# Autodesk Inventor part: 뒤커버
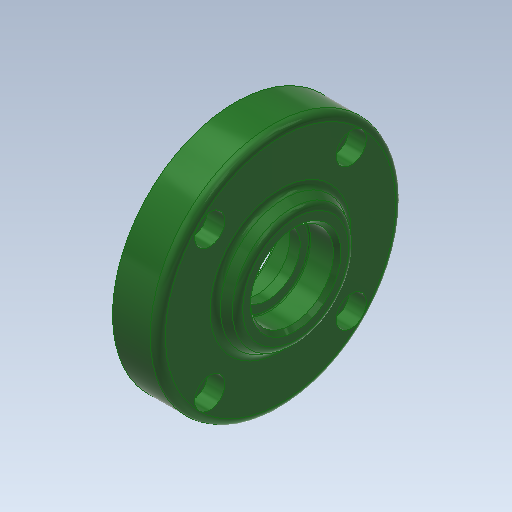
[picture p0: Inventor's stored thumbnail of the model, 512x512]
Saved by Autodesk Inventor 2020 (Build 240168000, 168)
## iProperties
Created: 2015-12
Part Number: 뒤커버
Document SubType Name: Modeling
Designer: mdu
Density: 2.71 g/cm^3
Mass: 96.0617 g
Surface Area: 117.44 cm^2
Volume: 35.4471 cm^3
Material: 알루미늄-6061
Appearance: 매끄러움 - 짙은 산림 녹색
Company: 한국ATC센터
Author: mdu
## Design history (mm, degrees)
sketch "스케치1"
  geometry: L1 (-10.5, 0)-(10.5, 0); L2 (10.5, 0)-(10.5, 22.5); L3 (10.5, 22.5)-(5.5, 22.5); L4 (5.5, 22.5)-(5.5, 32.5); L5 (5.5, 32.5)-(-6.5, 32.5); L6 (-6.5, 32.5)-(-6.5, 17.5); L7 (-6.5, 17.5)-(-10.5, 15.191); L8 (-10.5, 15.191)-(-10.5, 0); 2 further points
  constraints: 16 end point, 3 parallel, 3 perpendicular, 1 coincident, 1 horizontal, 1 midpoint
  dimensions: "d0" = 21 distance of L1.start L1.end; "d1" = 65 diameter of L5 L1; "d2" = 45 diameter of L3 L1; "d3" = 35 diameter of L6.end L1; "d4" = 120 deg angle of L7 L6; "d5" = 12 distance of L4.end L5.end; "d6" = 5 distance of L2.end L3.end
revolve "회전1" sketch "스케치1" stored, may be unused: angle "d7" = 90 deg
sketch "스케치2"
  geometry: L1 (0, 0)-(32.5, 0); L2 (0, 0)-(18.738, 18.738); 1 further point
  constraints: 4 end point, 1 horizontal, 1 horizontal alignment, 1 other
  dimensions: "d8" = 45 deg angle of L1 L2; "d9" = 26.5 distance of L1.start L2.end
hole "구멍1" sketch "스케치2" at (18.738, 18.738) diameter "d10" = 4.5; stored, may be unused: countersink angle "d14" = 90 deg, drill point angle "d16" = 118 deg; dims "d11" = 6, "d12" = 8, "d13" = 4.6, "d15" = 8
fillet "모깎기1" dims "d20" = 2
hole "구멍2" diameter "d23" = 15; stored, may be unused: countersink angle "d27" = 90 deg, drill point angle "d29" = 0 deg; dims "d21" = 10, "d22" = 10, "d24" = 6, "d25" = 35, "d26" = 11, "d28" = 14
chamfer "모따기1" distance "d39" = 1; stored, may be unused: second distance "d40" = 2, angle "d41" = 45 deg
fillet "모깎기2" dims "d42" = 0.6
hole "구멍4" diameter "d46" = 17; stored, may be unused: countersink angle "d50" = 90 deg, drill point angle "d52" = 118 deg; dims "d44" = 10, "d45" = 10, "d47" = 6, "d48" = 22, "d49" = 7.3, "d51" = 8
chamfer "모따기2" distance "d53" = 1; stored, may be unused: second distance "d54" = 2, angle "d55" = 45 deg
fillet "모깎기3" dims "d56" = 0.3
node "솔리드1"
pattern_circular "원형 패턴1" dims angle "d18" = 360 deg
